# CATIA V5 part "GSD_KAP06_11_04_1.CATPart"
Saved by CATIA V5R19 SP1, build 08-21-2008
Part number: GSD_BLEND_05
Definition: Beispielmodell für die Funktion Übergang / Blend - Manuelle Verbindung.
Description: CATIA V5 Flächenmodellierung  Copyright (c) 2009 Maik Hertha IT Consultants
Bounding box of the stored display mesh (mm): x -164.511 to 102.98, y -20 to 224.611, z -30.362 to 45
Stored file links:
  \GSD_BUCH_UEBUNG\GSD_KAP06_11_04_1.CATPart
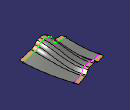
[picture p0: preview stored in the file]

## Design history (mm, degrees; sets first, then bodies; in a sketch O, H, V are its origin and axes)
AxisSystem1: origin (0, 0, 0), X (1, 0, 0), Y (0, 1, 0), Z (0, 0, 1)
Set1
  Sketch1 on ZX plane of AxisSystem1, origin (0, 0, 0), H (0, 0, 1), V (1, 0, 0)
    line L1 (-7.7811, 102.9804) -> (10.5771, 41.6998)
    arc A1 centre (44.1049, 51.744) radius 35 from (10.5771, 41.6998) to (24.809, 22.5435) ccw
    arc A2 centre (0, -15) radius 45 from (24.809, 22.5435) to (37.9923, 9.116) cw
    point P5 (0, -15)
    arc A3 centre (0, -15) radius 45 from (33.7014, -44.8197) to (4.0909, -59.8137) cw
    point P7 (0, -15)
    line L2 (-5, -69.7723) -> (-5, -121.1063)
    construction line L3 (70.2481, 0) -> (-64.8444, 0)
    point P8 (70.2481, 0)
    construction line L4 (0, 45.8622) -> (0, -41.9018)
    point P10 (0, 45.8622)
    curve C1
    arc A4 centre (5, -69.7723) radius 10 from (4.0909, -59.8137) to (-5, -69.7723) ccw
    arc A5 centre (0, -15) radius 45 from (37.9923, 9.116) to (43.6257, -3.9639) cw
    arc A6 centre (0, -15) radius 45 from (41.4452, -32.5298) to (33.7014, -44.8197) cw
    arc A7 centre (0, -15) radius 45 from (43.6257, -3.9639) to (41.4452, -32.5298) cw
    radius A3 = 45
    distance L4 L2 = 5
    distance P5 L3 = 15
    radius A4 = 10
    radius A1 = 35
    tangency: A1 L1, A2 A1, A3 A2, A4 L2, A4 A3
    vertical: L2 V, L4 V
    coincidence: P7 P5, P8 H, P10 V, P5 L4, A2 A5, A5 A6, A5 A7
    horizontal: L3 H
  Sketch2 on XY plane of AxisSystem1, origin (0, 0, 0), H (1, 0, 0), V (0, 1, 0)
    spline S1 through (63.5198, 0.6594) (52.4947, 108.5036) (27.7222, 201.6743)
    construction line L1 (63.5198, -33.9776) -> (63.5198, 23.4257)
    curve C1
    vertical: L1 V
  Plane1: type Normal, Curve Sketch2.C1, RefPoint {point type OnCurve, Support Sketch2.C1, Ratio 1}
  Sketch3 on Plane1, origin (27.7222, 201.6743, 0), H (-0.9497, -0.3131, 0), V (0, 0, 1)
    line L1 (-12.5925, -30.3622) -> (43.5645, -30.3622)
    line L2 (50.3453, -27.7121) -> (65.7944, -13.4594)
    line L3 (77.0077, -9.5205) -> (111.3244, -11.9105)
    line L4 (134.514, -21.3899) -> (139.6722, -25.7927)
    line L5 (149.4105, -29.3837) -> (195.8144, -29.3837)
    curve C1
    arc A1 centre (43.5645, -20.3622) radius 10 from (43.5645, -30.3622) to (50.3453, -27.7121) ccw
    arc A2 centre (75.9655, -24.4842) radius 15 from (65.7944, -13.4594) to (77.0077, -9.5205) cw
    arc A3 centre (108.5452, -51.8139) radius 40 from (111.3244, -11.9105) to (134.514, -21.3899) cw
    arc A4 centre (149.4105, -14.3837) radius 15 from (139.6722, -25.7927) to (149.4105, -29.3837) ccw
    radius A1 = 10
    radius A4 = 15
    radius A3 = 40
    radius A2 = 15
    horizontal: L1 H, L5 H
    tangency: A1 L1, A1 L2, A2 L2, A2 L3, A3 L3, A3 L4, A4 L4, A4 L5
  Extrude1: Lim1 20, Lim2 0, Element1 Sketch3.C1, Direction Plane1
  Extrude2: Lim1 20, Lim2 0, Element1 Sketch1.C1, Direction zx-plane
Set2
  Blend1: StartLimit {blendlimit Support Extrude2, Curve Sketch1.C1}, LimitCouplingPoints ({coupling CouplingPoints ({point type OnCurve, Support Sketch1.C1, Length 201.4825}; {point type OnCurve, Support Sketch3.C1, Length 164.3558})}; {coupling CouplingPoints ({point type OnCurve, Support Sketch1.C1, Length 177.1297}; {point type OnCurve, Support Sketch3.C1, Length 156.9044})}; {coupling CouplingPoints ({point type OnCurve, Support Sketch1.C1, Length 158.1724}; {point type OnCurve, Support Sketch3.C1, Length 135.885})}; {coupling CouplingPoints ({point type OnCurve, Support Sketch1.C1, Length 143.8707}; {point type OnCurve, Support Sketch3.C1, Length 123.6648})}; {coupling CouplingPoints ({point type OnCurve, Support Sketch1.C1, Length 114.7145}; {point type OnCurve, Support Sketch3.C1, Length 89.265})}; {coupling CouplingPoints ({point type OnCurve, Support Sketch1.C1, Length 100.1245}; {point type OnCurve, Support Sketch3.C1, Length 63.784})}; {coupling CouplingPoints ({point type OnCurve, Support Sketch1.C1, Length 66.1317}; {point type OnCurve, Support Sketch3.C1, Length 57.0023})}; {coupling CouplingPoints ({point type OnCurve, Support Sketch1.C1, Length 51.3341}; {point type OnCurve, Support Sketch3.C1, Length 46.4039})}), EndLimit {blendlimit Support Extrude1, Curve Sketch3.C1}
Body1 (main body)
